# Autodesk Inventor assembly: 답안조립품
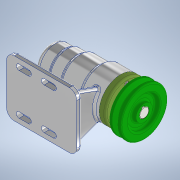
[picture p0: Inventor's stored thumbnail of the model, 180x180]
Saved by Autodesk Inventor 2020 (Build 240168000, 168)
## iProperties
Created: 2021-10
Part Number: 답안조립품
Document SubType Name: Assembly
Designer: user
Author: user
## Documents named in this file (12)
- C:\Users\user\Desktop\711007V1013\답안조립품.iam
- C:\Users\user\Desktop\711007V1013\V벨트풀리.ipt
- C:\Users\user\Desktop\711007V1013\멈춤나사 M3.ipt
- C:\Users\user\Desktop\711007V1013\베어링 6004.ipt
- C:\Users\user\Desktop\711007V1013\베어링 51202.ipt
- C:\Users\user\Desktop\711007V1013\본체.ipt
- C:\Users\user\Desktop\711007V1013\볼트 M4.ipt
- C:\Users\user\Desktop\711007V1013\어댑터슬리브.ipt
- C:\Users\user\Desktop\711007V1013\오일 실 20x35x7.ipt
- C:\Users\user\Desktop\711007V1013\축.ipt
- C:\Users\user\Desktop\711007V1013\커버.ipt
- C:\Users\user\Desktop\711007V1013\키 5x5.ipt
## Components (1 placed, 1 different names)
1. V벨트풀리:1
